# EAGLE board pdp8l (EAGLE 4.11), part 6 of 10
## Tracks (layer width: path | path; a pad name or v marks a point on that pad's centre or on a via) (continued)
MB_PARITY_ODD  (via drill 0.61) (continued)
  Route15 0.203: v162.97,264.82 163.37,264.82 165.81,262.38 171.91,262.38 211.73,222.56 211.73,221.34 232.87,200.2 233.68,200.2 246.69,187.2 246.69,185.57 250.75,181.51 250.75,179.48 251.97,178.26 B17.K1
  Bottom 0.203: v162.97,264.82 155.25,264.82 154.43,264.01 A24.D2
MEM00  (via drill 0.61)
  Top 0.203: v296.27,95.76 298.3,93.73 298.3,79.5 301.14,76.66 301.14,64.47 301.95,63.65 301.95,27.08 300.74,25.86 D13.R1 | v374.7,145.75 375.11,146.15 375.11,160.38 375.92,161.19 AB07.BR1 | v298.7,145.34 299.11,144.93 v299.11,138.02 | v267,138.84 266.6,138.43 266.6,131.93 265.38,130.71 C16.C1 | v26.82,272.95 26.82,272.54 19.1,264.82 19.1,194.92 19.91,194.11 B35.D1 | v239.78,281.48 239.78,273.76 A18.A1 240.18,272.54 241,271.73 241,205.49 244.65,201.83 244.65,177.44 v243.84,176.63 | v276.35,281.89 276.35,262.38 277.57,261.16 A15.E1
  Route15 0.203: v296.27,95.76 265.38,126.64 265.38,129.49 C16.C1 | v240.18,173.79 244.25,169.72 244.25,163.63 258.47,149.4 258.88,149.4 262.94,145.34 262.94,144.53 267,140.46 267,139.24 v267,138.84
  Bottom 0.203: v374.7,145.75 374.29,145.34 369.42,145.34 369.01,144.93 351.54,144.93 351.13,145.34 350.32,145.34 349.5,144.53 321.87,144.53 320.65,145.75 309.68,145.75 309.27,145.34 v298.7,145.34 | v299.11,138.02 298.7,138.43 288.54,138.43 287.73,139.24 267.41,139.24 v267,138.84 | v26.82,272.95 32.11,278.23 100.38,278.23 102.41,280.26 167.44,280.26 168.66,281.48 v239.78,281.48 239.78,281.89 251.16,281.89 251.97,281.08 252.78,281.08 253.19,281.48 253.19,281.89 253.59,282.3 275.95,282.3 v276.35,281.89 | v240.18,173.79 243.03,176.63 v243.84,176.63
MEM00\  (via drill 0.61)
  Top 0.203: v254.81,137.62 254.41,137.21 254.41,128.27 255.22,127.46 C16.D2
  Route2 0.203: v195.48,201.42 196.7,202.64 196.7,203.86 202.79,209.96 202.79,212.8 210.92,220.93 211.33,220.93 212.95,222.56 212.95,222.96 250.34,260.35 250.75,260.35 254.41,264.01 254.41,264.41 264.57,274.57 275.95,274.57 277.17,273.36 A15.A1
  Route15 0.203: v254.81,137.62 249.94,142.49 249.94,144.53 225.55,168.91 225.55,170.94 195.48,201.02 v195.48,201.42
MEM01  (via drill 0.61)
  Top 0.203: 363.32,136.8 366.57,140.06 v366.57,148.59 | 363.32,136.8 362.1,135.59 362.1,126.24 360.48,124.61 C08.E2 | v25.6,205.08 25.6,195.73 25.2,195.33 25.2,192.48 23.98,191.26 B35.E1 | v52.83,205.08 53.24,205.49 v53.24,216.05 | v232.46,216.05 232.87,216.46 232.87,221.74 A18.U2 233.68,222.96 234.9,224.18 234.9,249.38 v234.49,249.78 | 263.35,144.93 263.35,164.03 260.5,166.88 260.5,206.7 v260.1,207.11 | 263.35,144.93 263.35,128.27 262.53,127.46 C16.D1 | v273.51,249.78 273.51,255.88 274.32,256.69 A15.F1 | 363.32,136.8 359.26,140.87 v359.26,144.12 | v263.75,144.93 263.35,144.93
  Bottom 0.203: v366.57,148.59 369.42,148.59 AB07.BV2 | v52.83,205.08 v25.6,205.08 | v53.24,216.05 53.65,216.46 193.45,216.46 193.85,216.05 219.46,216.05 | 219.46,216.05 v232.46,216.05 | v260.1,207.11 259.69,206.7 248.72,206.7 248.31,206.3 236.93,206.3 228.8,214.43 221.08,214.43 219.46,216.05 | v273.51,249.78 273.1,249.38 234.9,249.38 v234.49,249.78 | v359.26,144.12 358.85,143.71 308.86,143.71 308.05,144.53 300.33,144.53 299.92,144.12 290.17,144.12 289.76,144.53 264.16,144.53 v263.75,144.93
MEM01\  (via drill 0.61)
  Top 0.203: v182.88,119.33 181.25,120.95 181.25,181.91 180.85,182.32 180.85,185.17 181.25,185.57 181.25,249.78 199.95,268.48 212.55,268.48 v212.55,268.88
  Bottom 0.203: v182.88,119.33 199.14,119.33 204.83,125.02 259.69,125.02 260.1,124.61 264.16,124.61 264.57,124.21 C16.E1 | v212.55,268.88 215.8,268.88 216.61,268.07 238.15,268.07 238.96,268.88 241,268.88 241.81,268.07 262.53,268.07 263.35,268.88 267.41,268.88 267.82,268.48 272.69,268.48 273.91,269.7 A15.B1
MEM02  (via drill 0.61)
  Top 0.203: v274.32,275.79 275.95,274.17 275.95,256.29 277.57,254.66 A15.H1 | C16.E2 258.47,124.61 257.25,125.83 v257.25,137.21 257.25,137.62 257.25,147.37 v257.66,147.78 | v23.98,179.48 23.98,183.54 B35.H1 | v388.52,138.43 390.14,140.06 390.14,160.38 389.33,161.19 AB06.BR1 | v215.39,231.09 215.8,231.5 215.8,251 225.55,260.76 225.55,271.73 226.37,272.54 A19.A1 | v262.94,183.95 263.75,183.13 263.75,168.5 266.6,165.66 266.6,151.84 265.38,150.62 v265.38,148.59
  Route2 0.203: v388.52,138.43 384.86,138.43 361.29,114.86 360.88,114.86 360.48,114.45 360.48,113.64 361.29,112.83 362.92,114.45 C08.J1
  Route15 0.203: v332.84,138.02 337.72,138.02 347.07,128.68 351.13,128.68 361.7,118.11 361.7,116.48 363.32,114.86 C08.J1 | v23.98,179.48 24.38,179.48 53.65,150.22 53.65,149.4 v57.3,145.75 | v215.39,231.09 215.39,229.87 225.55,219.71 226.37,219.71 239.37,206.7 240.18,206.7 v262.94,183.95
  Bottom 0.203: v274.32,275.79 273.91,275.39 229.62,275.39 227.58,273.36 A19.A1 | v257.25,137.21 258.06,138.02 275.13,138.02 275.95,138.84 287.32,138.84 288.14,138.02 297.89,138.02 299.11,136.8 301.55,136.8 302.77,138.02 319.84,138.02 320.24,137.62 321.46,137.62 321.87,138.02 v332.84,138.02 | v57.3,145.75 58.52,144.53 70.31,144.53 71.12,143.71 83.72,143.71 84.12,143.31 102.01,143.31 102.82,144.12 123.55,144.12 125.17,145.75 127.61,145.75 128.42,144.93 130.45,144.93 131.27,144.12 167.84,144.12 169.06,145.34 176.38,145.34 177.19,144.53 206.04,144.53 206.45,144.93 236.12,144.93 237.34,146.15 251.16,146.15 252.78,147.78 v257.66,147.78 258.06,147.78 264.57,147.78 v265.38,148.59
MEM02\  (via drill 0.61)
  Top 0.203: v253.59,143.71 254,143.31 254,122.58 255.22,121.36 C16.F2
  Route2 0.203: v253.59,143.71 253.59,145.34 258.47,150.22 v258.88,150.22 | v216.21,203.45 216.21,205.49 228.4,217.68 228.4,219.3 273.91,264.82 275.54,264.82 277.17,266.45 A15.C1
  Route15 0.203: v258.88,150.22 244.65,164.44 244.65,170.13 244.25,170.54 244.25,171.35 228.8,186.79 228.8,190.86 v216.21,203.45
MEM03  (via drill 0.61)
  Top 0.203: v238.96,147.78 238.56,148.18 238.56,175.01 238.15,175.41 238.15,188.42 237.74,188.82 v237.74,207.11 | v221.49,215.24 221.08,215.65 221.08,221.74 A19.U2 | v20.73,146.15 19.51,147.37 19.51,179.48 20.32,180.29 B35.J1 | v275.54,214.83 275.95,215.24 275.95,249.38 275.13,250.19 A15.J1 | v381.2,160.78 381.2,150.62 382.02,149.81 AB06.BV2
  Route2 0.203: v358.44,160.78 358.04,160.78 354.38,157.12 354.38,156.72 351.94,154.28 347.47,154.28 340.56,147.37 337.31,147.37 327.15,137.21 327.15,133.15 318.21,124.21 v317.81,124.21
  Route15 0.203: v238.96,147.78 250.75,135.99 250.75,135.18 261.72,124.21 261.72,121.36 C16.F1
  Bottom 0.203: v221.49,215.24 229.62,215.24 v237.74,207.11 237.74,206.7 247.9,206.7 256.85,215.65 263.35,215.65 264.16,214.83 v275.54,214.83 | v20.73,146.15 21.13,146.56 49.58,146.56 49.99,146.15 56.49,146.15 56.9,146.56 69.49,146.56 70.31,145.75 84.12,145.75 84.94,144.93 98.35,144.93 98.75,144.53 100.79,144.53 102.01,145.75 117.86,145.75 119.89,147.78 120.7,147.78 121.11,147.37 134.93,147.37 136.55,145.75 166.22,145.75 167.44,146.96 177.19,146.96 177.6,147.37 180.44,147.37 181.66,146.15 232.46,146.15 233.68,147.37 238.96,147.37 v238.96,147.78 | v358.44,160.78 v381.2,160.78 | v317.81,124.21 318.62,123.39 318.62,122.17 316.99,122.17 316.59,122.58 306.02,122.58 304.8,121.36 301.14,121.36 299.92,122.58 264.16,122.58 262.53,120.95 C16.F1
MEM03\  (via drill 0.61)
  Top 0.203: v206.86,168.5 206.45,168.91 206.45,214.02 209.7,217.27 209.7,220.52 v210.92,221.74
  Route2 0.203: v250.34,261.16 v210.92,221.74
  Route15 0.203: v206.86,168.5 230.43,144.93 234.9,144.93 262.13,117.7 264.57,117.7 C16.H1
  Bottom 0.203: v250.34,261.16 251.16,261.98 272.69,261.98 273.91,263.2 A15.D1
MEM04  (via drill 0.61)
  Top 0.203: v241,146.96 242.62,145.34 v242.62,135.18 | v288.54,157.53 286.11,157.53 v286.11,154.28 | A16.P2 258.47,234.34 257.66,233.53 257.66,229.46 257.25,229.06 257.25,224.18 256.85,223.77 256.85,138.02 256.44,137.62 256.44,134.77 256.85,134.37 256.85,119.74 258.47,118.11 C16.H2
  Route2 0.203: v402.34,166.06 401.93,165.66 401.93,162.41 AB05.BR1
  Route15 0.203: v60.96,145.75 60.15,144.93 56.9,144.93 54.05,147.78 51.61,147.78 36.58,162.81 35.36,162.81 34.95,163.22 34.95,163.63 24.38,174.19 21.13,174.19 B35.L1 | v242.62,135.18 243.03,135.18 256.85,121.36 256.85,119.74 258.47,118.11 C16.H2 | A20.A1 214.99,272.95 217.83,272.95 222.71,268.07 223.52,268.07 251.56,240.03 255.63,240.03 256.85,238.81 256.85,237.19 258.47,235.56 A16.P2
  Bottom 0.203: v60.96,145.75 61.37,145.34 71.53,145.34 72.34,144.53 97.94,144.53 98.35,144.12 101.19,144.12 102.41,145.34 123.14,145.34 124.36,146.56 131.27,146.56 132.89,144.93 167.03,144.93 168.25,146.15 177.19,146.15 177.6,145.75 232.87,145.75 234.09,146.96 v241,146.96 241.4,146.96 242.62,146.96 246.28,150.62 249.94,150.62 250.34,150.22 254,150.22 254.81,151.03 280.42,151.03 283.26,153.87 285.7,153.87 v286.11,154.28 | v402.34,166.06 401.52,166.88 338.53,166.88 337.72,166.06 336.09,166.06 335.69,166.47 319.84,166.47 314.15,160.78 310.9,160.78 309.68,162 308.05,162 306.83,163.22 297.08,163.22 291.39,157.53 v288.54,157.53
MEM04\  (via drill 0.61)
  Top 0.203: v250.34,171.75 250.75,171.35 250.75,153.47 247.9,150.62 247.9,148.18 253.59,142.49 253.59,116.48 255.22,114.86 C16.J2
  Route2 0.203: v222.71,202.64 237.74,217.68 237.74,218.49 244.25,224.99 244.25,229.06 255.63,240.44 255.63,242.47 256.85,243.69 256.85,245.31 258.47,246.94 A16.K2
  Route15 0.203: v250.34,171.75 247.9,174.19 247.9,177.85 230.84,194.92 226.77,194.92 222.71,198.98 v222.71,202.64
MEM05  (via drill 0.61)
  Top 0.203: v208.08,216.86 208.08,221.74 A20.U2 | A16.R2 255.22,231.09 254,229.87 254,218.49 v252.37,216.86 252.37,216.46 254,214.83 254,185.57 256.03,183.54 v256.03,183.13 | v395.43,146.96 395.43,148.59 AB05.BV2 | v25.6,145.34 25.6,169.72 24.38,170.94 B35.M1 | v269.85,169.32 270.26,168.91 v270.26,147.37
  Route2 0.203: v289.36,146.15 270.66,127.46 270.66,125.02 262.53,116.89 262.53,114.86 C16.J1
  Route15 0.203: v269.85,169.32 v256.03,183.13
  Bottom 0.203: v252.37,216.86 v208.08,216.86 | v395.43,146.96 395.02,147.37 356.82,147.37 356.01,146.56 349.1,146.56 348.29,145.75 325.12,145.75 323.09,147.78 321.06,147.78 320.24,146.96 317.4,146.96 316.59,147.78 312.12,147.78 311.71,148.18 308.46,148.18 306.43,146.15 v289.36,146.15 288.95,146.15 287.73,146.15 287.32,146.56 270.26,146.56 | v25.6,145.34 26.42,144.53 57.71,144.53 58.12,144.12 69.9,144.12 71.12,142.9 102.41,142.9 103.23,143.71 123.95,143.71 125.58,145.34 127.2,145.34 128.02,144.53 130.05,144.53 130.86,143.71 206.86,143.71 207.67,144.53 237.34,144.53 238.56,145.75 253.19,145.75 254,146.56 270.26,146.56 | 270.26,146.56 v270.26,147.37
MEM05\  (via drill 0.61)
  Top 0.203: v222.3,159.16 221.89,159.56 221.89,207.92 223.11,209.14 223.11,216.05 221.89,217.27 v221.89,220.52
  Route2 0.203: v221.89,220.52 v244.65,243.28
  Route15 0.203: v222.3,159.16 244.65,136.8 244.65,135.99 261.72,118.92 265.79,118.92 267.41,117.3 265.79,115.67 265.79,111.61 C16.K1
  Bottom 0.203: v244.65,243.28 254,243.28 254.81,244.09 A16.L2
MEM06  (via drill 0.61)
  Top 0.203: A16.S2 258.47,227.84 258.47,224.59 257.25,223.37 257.25,205.49 v257.66,205.08 257.66,204.67 257.25,204.27 257.25,149.4 259.28,147.37 259.28,146.15 v259.28,145.75 258.88,145.34 258.88,138.43 260.1,137.21 260.1,112.42 259.28,111.61 C16.K2 | v30.48,166.88 32.11,165.25 32.11,142.49 v33.33,141.28 | v415.75,143.71 415.75,159.97 414.53,161.19 AB04.BR1
  Bottom 0.203: v257.66,205.08 241.4,205.08 240.18,203.86 B18.A1 | v30.48,166.88 25.6,166.88 24.38,165.66 B35.P1 | v33.33,141.28 33.73,140.87 90.63,140.87 91.85,142.09 112.98,142.09 113.79,142.9 123.95,142.9 124.36,142.49 125.17,142.49 125.58,142.9 125.58,144.53 125.98,144.93 126.8,144.93 127.61,144.12 128.42,144.12 129.24,143.31 207.26,143.31 208.08,144.12 237.74,144.12 238.96,145.34 253.59,145.34 254,145.75 v259.28,145.75 259.69,145.75 261.31,144.12 289.36,144.12 289.76,143.71 300.33,143.71 300.74,144.12 307.64,144.12 308.46,143.31 360.88,143.31 361.7,144.12 365.76,144.12 366.17,143.71 373.07,143.71 373.48,144.12 392.58,144.12 393.8,142.9 414.93,142.9 v415.75,143.71
MEM06\  (via drill 0.61)
  Route2 0.203: v277.17,149.81 277.17,142.49 272.69,138.02 272.69,135.59 270.26,133.15 270.26,125.42 255.63,110.79 255.63,108.76 C16.L2 | v227.18,213.21 v254.81,240.84
  Route15 0.203: v277.17,149.81 277.17,150.22 262.53,164.85 262.53,165.66 254.41,173.79 254.41,179.07 249.53,183.95 249.53,185.17 247.9,186.79 247.9,191.26 234.09,205.08 234.09,206.3 v227.18,213.21
  Bottom 0.203: v254.81,240.84 258.06,240.84 A16.M2
MEM07  (via drill 0.61)
  Top 0.203: v233.27,139.65 233.27,151.84 B18.U2 232.87,153.06 232.05,153.87 232.05,174.6 231.24,175.41 231.24,177.04 v230.43,177.85 | v407.62,144.53 407.62,148.59 AB04.BV2 | v210.92,135.18 212.14,136.4 v212.14,139.24 | v255.22,203.05 256.03,203.86 256.03,217.68 254.81,217.68 254.41,218.08 254.41,224.18 255.22,224.99 A16.T2
  Route2 0.203: v372.67,144.53 371.86,144.53 350.72,123.39 350.32,123.39 349.91,122.99 349.91,121.77 v341.38,113.23 | v255.22,203.05 230.43,178.26 v230.43,177.85
  Route15 0.203: v233.27,139.65 258.06,114.86 258.06,114.45 261.72,110.79 261.72,108.76 C16.L1 | v103.63,159.97 107.29,159.97 117.04,150.22 117.04,149 v129.24,136.8
  Bottom 0.203: v407.62,144.53 407.21,144.93 386.49,144.93 386.08,144.53 v372.67,144.53 | v341.38,113.23 340.56,112.42 325.93,112.42 323.49,109.98 287.73,109.98 285.29,112.42 268.22,112.42 264.16,108.36 262.53,108.36 C16.L1 | v103.63,159.97 25.2,159.97 24.38,159.16 B35.S1 | v129.24,136.8 130.86,135.18 v210.92,135.18 | v212.14,139.24 212.55,139.65 232.87,139.65 v233.27,139.65
MEM07\  (via drill 0.61)
  Top 0.203: v224.74,112.01 225.15,112.42 225.15,129.08 219.46,134.77 219.46,172.16 219.86,172.57 219.86,176.63 219.46,177.04 219.46,206.7 v222.3,209.55
  Route2 0.203: v222.3,209.55 230.43,217.68 230.84,217.68 251.97,238.81 v251.97,239.22
  Bottom 0.203: v224.74,112.01 225.15,112.42 254.41,112.42 260.1,106.73 269.04,106.73 269.44,106.32 269.44,105.51 269.04,105.1 265.79,105.1 C16.M1 | v251.97,239.22 252.78,238.4 254.81,238.4 A16.N2
MEM08  (via drill 0.61)
  Top 0.203: v257.25,114.45 257.25,106.73 258.47,105.51 C16.M2 | v233.27,138.43 234.49,139.65 234.49,145.75 | 234.49,145.75 234.49,179.48 234.9,179.88 234.9,198.17 234.49,198.58 | 234.49,198.58 233.27,199.8 v233.27,201.02 | v234.09,145.75 234.49,145.75 | v269.85,216.05 269.85,233.12 271.07,234.34 A15.P2 | v234.49,216.05 234.09,215.65 234.09,204.67 234.49,204.27 234.49,198.58
  Route2 0.203: v417.78,149.81 426.72,158.75 426.72,161.19 AB03.BR1 | v329.59,146.56 329.59,146.15 318.62,135.18 318.21,135.18 305.21,122.17 305.21,121.77 v301.14,117.7
  Route15 0.203: v257.25,114.45 257.25,114.86 233.68,138.43 v233.27,138.43 | v59.74,145.75 36.58,168.91 36.58,169.32 14.63,191.26 14.63,192.89 B35.D2
  Bottom 0.203: v233.27,201.02 231.65,202.64 227.58,202.64 B19.A1 | v417.78,149.81 414.93,146.96 396.65,146.96 395.83,147.78 354.38,147.78 353.57,146.96 348.69,146.96 347.88,146.15 330,146.15 v329.59,146.56 | v301.14,117.7 299.52,116.08 278.38,116.08 275.13,112.83 259.28,112.83 257.66,114.45 v257.25,114.45 | v59.74,145.75 60.55,144.93 70.71,144.93 71.53,144.12 84.12,144.12 84.53,143.71 101.6,143.71 102.41,144.53 123.14,144.53 124.77,146.15 128.02,146.15 128.83,145.34 130.86,145.34 131.67,144.53 167.44,144.53 168.66,145.75 176.78,145.75 177.6,144.93 205.64,144.93 206.04,145.34 233.68,145.34 v234.09,145.75 | v234.49,216.05 v269.85,216.05
MEM08\  (via drill 0.61)
  Top 0.203: v208.08,150.22 206.04,152.25 206.04,222.56 213.77,230.28 218.64,230.28 218.64,241.25 v221.49,244.09
  Route15 0.203: v208.08,150.22 220.27,138.02 221.08,138.02 222.3,136.8 222.3,135.59 222.71,135.18 222.71,132.33 253.19,101.85 254.81,101.85 C16.N2
  Bottom 0.203: v221.49,244.09 223.11,245.72 235.31,245.72 235.71,246.13 269.44,246.13 270.66,247.34 A15.K2
MEM09  (via drill 0.61)
  Top 0.203: v223.11,135.99 221.08,138.02 221.08,151.84 B19.U2 | v416.56,131.93 419.81,135.18 419.81,148.18 420.22,148.59 AB03.BV2 | v303.17,103.07 302.77,102.67 v302.77,101.04 | v18.69,151.44 19.1,151.84 19.1,188.82 17.88,190.04 B35.E2 | v98.35,146.56 98.75,146.96 98.75,155.91 v99.57,156.72
  Route2 0.203: v352.75,133.55 352.75,133.15 v324.71,105.1 | v254.81,228.65 205.64,179.48 201.17,179.48 197.1,175.41 197.1,170.94 v185.32,159.16
  Route15 0.203: v254,105.1 v223.11,135.99
  Bottom 0.203: 260.1,103.07 259.69,103.48 255.63,103.48 v254,105.1 | 260.1,103.07 261.31,101.85 C16.N1 | v416.56,131.93 393.39,131.93 392.99,132.33 390.14,132.33 389.74,131.93 355.19,131.93 353.57,133.55 v352.75,133.55 | v324.71,105.1 323.09,103.48 303.58,103.48 v303.17,103.07 | v302.77,101.04 300.74,103.07 272.69,103.07 271.88,102.26 269.85,102.26 269.04,103.07 260.1,103.07 | v18.69,151.44 18.69,147.78 69.09,147.78 70.31,146.56 v98.35,146.56 | v99.57,156.72 99.97,157.12 129.64,157.12 130.05,157.53 154.03,157.53 156.46,159.97 174.75,159.97 175.16,160.38 177.6,160.38 181.25,156.72 185.32,156.72 | 185.32,156.72 201.57,156.72 204.42,153.87 210.92,153.87 213.77,151.03 218.64,151.03 219.86,152.25 B19.U2 | v254.81,228.65 256.44,230.28 262.53,230.28 262.94,230.68 267.41,230.68 267.82,231.09 A15.R2 | 185.32,156.72 v185.32,159.16
MEM09\  (via drill 0.61)
  Top 0.203: v258.06,214.83 260.5,217.27 260.5,233.53 v262.94,235.97
  Route2 0.203: v206.45,148.59 206.45,161.19 218.24,172.97 218.24,173.38 225.15,180.29 225.15,184.35 245.47,204.67 247.9,204.67 v258.06,214.83 | v262.94,235.97 264.57,237.59 264.57,238.81 266.6,240.84 266.6,242.06 268.22,243.69 A15.L2
  Route15 0.203: v254,98.6 254,99.01 249.94,103.07 245.87,103.07 216.21,132.74 216.21,138.84 v206.45,148.59
  Bottom 0.203: v254,98.6 255.63,98.6 256.85,99.82 263.75,99.82 264.57,99.01 C16.P1
MEM10  (via drill 0.61)
  Top 0.203: v212.55,134.37 212.95,134.77 212.95,201.83 213.77,202.64 B20.A1 214.58,203.86 214.58,205.49 v216.21,207.11 | v100.38,188.01 102.01,189.64 v102.01,198.58 | v268.63,210.36 268.63,211.58 270.66,213.61 270.66,216.46 270.26,216.86 270.26,227.03 271.07,227.84 A15.S2
  Route2 0.203: v384.86,162.41 382.02,165.25 364.54,147.78 361.29,147.78 349.5,135.99 349.5,135.59 v334.47,120.55
  Route15 0.203: v212.55,134.37 v230.02,116.89 254.81,92.1 258.47,95.76 258.47,97.79 C16.P2
  Bottom 0.203: v384.86,162.41 386.89,160.38 438.51,160.38 439.32,161.19 AB02.BR1 | v334.47,120.55 333.25,119.33 232.46,119.33 v230.02,116.89 | v100.38,188.01 88.59,176.22 66.24,176.22 63.4,179.07 54.86,179.07 54.46,178.66 53.24,178.66 53.24,179.88 53.65,180.29 53.65,181.51 52.83,182.32 42.67,182.32 39.42,185.57 18.69,185.57 17.88,184.76 B35.H2 | v102.01,198.58 125.17,198.58 128.42,201.83 133.3,201.83 133.71,202.23 136.96,202.23 137.77,201.42 156.87,201.42 159.72,198.58 162.15,198.58 162.56,198.98 165.81,198.98 166.22,198.58 174.75,198.58 177.6,201.42 194.26,201.42 195.07,200.61 197.1,200.61 198.32,201.83 212.95,201.83 213.77,202.64 B20.A1 | v268.63,210.36 264.57,206.3 249.12,206.3 248.72,205.89 236.53,205.89 235.71,206.7 216.61,206.7 v216.21,207.11
MEM10\  (via drill 0.61)
  Top 0.203: v218.24,135.59 218.64,135.99 218.64,172.16 218.24,172.57 218.24,173.38 218.64,173.79 v218.64,198.58
  Route2 0.203: v218.64,198.58 220.27,198.58 226.37,204.67 227.18,204.67 237.34,214.83 237.34,216.46 238.15,217.27 238.15,218.08 v259.69,239.62
  Route15 0.203: v218.24,135.59 255.22,98.6 255.22,95.76 C16.R2
  Bottom 0.203: v259.69,239.62 260.1,240.03 269.44,240.03 270.66,241.25 A15.M2
MEM11  (via drill 0.61)
  Top 0.203: v161.34,153.87 166.62,153.87 v166.62,151.03 | v227.58,220.52 227.99,220.12 227.99,206.3 225.55,203.86 v225.55,172.16
  Route2 0.203: v225.55,172.16 209.7,156.31 209.7,154.69 208.08,153.06 B20.U2 | v271.48,227.03 270.26,227.03 269.04,225.81 A15.T2
  Route15 0.203: C16.R1 261.31,95.76 261.31,99.01 223.52,136.8 223.52,138.84 211.73,150.62 209.7,150.62 208.48,151.84 B20.U2 | v54.86,175.41 56.08,175.41 v79.25,152.25 | v398.27,144.12 394.21,140.06 344.63,189.64 344.63,191.67 333.25,203.05 333.25,203.45 332.84,203.86 331.62,203.86 323.9,211.58 323.49,211.58 v306.83,228.24
  Bottom 0.203: v54.86,175.41 54.46,175.82 49.17,175.82 46.74,173.38 17.48,173.38 17.48,177.04 B35.K2 | v79.25,152.25 79.25,153.87 v161.34,153.87 | v166.62,151.03 206.04,151.03 207.26,152.25 B20.U2 | v227.58,220.52 229.62,220.52 232.87,223.77 240.18,223.77 241,222.96 243.84,222.96 245.06,224.18 262.94,224.18 263.35,224.59 267.41,224.59 267.82,224.99 A15.T2 | v398.27,144.12 398.68,143.71 408.03,143.71 408.84,144.53 428.35,144.53 432.82,149 AB02.BV2 | v306.83,228.24 306.43,227.84 304.39,227.84 303.99,227.43 294.64,227.43 294.23,227.84 291.8,227.84 291.39,227.43 282.04,227.43 281.63,227.84 279.2,227.84 278.38,227.03 v271.48,227.03
MEM11\  (via drill 0.61)
  Top 0.203: v224.33,137.21 222.71,138.84 222.71,158.34 223.11,158.75 223.11,160.78 222.3,161.59 222.3,182.32 v224.33,184.35 | v261.31,220.93 263.35,222.96 263.35,235.15 263.75,235.56 v263.75,238
  Route2 0.203: v224.33,184.35 245.06,205.08 246.28,205.08 252.78,211.58 252.78,212.39 v261.31,220.93
  Route15 0.203: v224.33,137.21 264.16,97.38 264.16,95.35 264.57,94.94 264.57,92.51 C16.S1
  Bottom 0.203: v263.75,238 267.82,238 A15.N2
MEM_ALT1\  (via drill 0.61)
  Top 0.203: v338.12,235.97 336.91,237.19 336.91,241.25 339.34,243.69 339.34,253.85 338.53,254.66 338.53,256.69 A10.F1 | v430.78,94.13 428.75,96.16 428.75,103.07 v429.16,103.48
  Route2 0.203: v338.12,235.97 338.12,235.56 332.03,229.46 332.03,226.21 A10.T2 | v449.48,63.65 441.76,55.93 441.76,54.71 437.69,50.65 437.69,46.58 419.81,28.7 418.19,28.7 D04.P1
  Route15 0.203: v449.48,63.65 449.48,64.47 447.85,66.09 447.85,68.94 444.6,72.19 444.6,79.91 433.22,91.29 432.82,91.29 432.41,91.69 432.41,92.51 v430.78,94.13 | v429.16,103.48 403.56,129.08 403.56,140.87 397.87,146.56 397.87,150.22 396.65,151.44 396.65,152.25 387.71,161.19 387.71,165.25 358.04,194.92 353.97,194.92 346.25,202.64 346.25,204.27 343.81,206.7 343.41,206.7 343,207.11 343,207.92 337.72,213.21 337.72,217.27 336.5,218.49 336.5,218.9 333.65,221.74 333.65,223.77 332.44,224.99 A10.T2
MEM_ALT2\  (via drill 0.61)
  Top 0.203: v321.06,224.18 321.06,230.68 321.87,231.5 321.87,234.34 A11.P2 | v418.59,63.25 418.59,62.84 419.81,61.62 419.81,59.18 419.4,58.78 419.4,47.4 416.15,44.15 416.15,27.08 414.93,25.86 D04.R1
  Route2 0.203: v418.59,63.25 418.59,63.65 426.72,71.78 426.72,72.59 449.88,95.76 449.88,96.98 450.7,97.79 450.7,102.26 451.92,103.48 451.92,104.7 v455.17,107.95 | v313.33,234.34 312.52,234.34 310.08,231.9 310.08,231.09 308.05,229.06 308.05,227.84 306.43,226.21 A12.T2
  Route15 0.203: v455.17,107.95 453.14,109.98 453.14,110.39 452.73,110.79 452.32,110.79 451.51,111.61 451.51,113.23 447.85,116.89 447.85,120.95 443.79,125.02 443.79,127.05 435.25,135.59 435.25,138.02 419,154.28 419,155.09 416.15,157.94 416.15,163.22 391.36,188.01 v391.36,188.42 | v360.88,188.01 359.26,188.01 339.75,207.52 339.75,210.36 337.31,212.8 337.31,215.65 329.18,223.77 324.71,223.77 321.06,227.43 321.06,229.06 320.24,229.87 319.02,229.87 317.4,231.5 317.4,231.9 315.77,233.53 314.15,233.53 v313.33,234.34
  Bottom 0.203: v321.06,224.18 307.64,224.18 306.83,224.99 A12.T2 | v391.36,188.42 388.93,190.86 387.3,190.86 386.08,192.07 366.17,192.07 362.1,188.01 v360.88,188.01
MEM_BEGIN\  (via drill 0.61)
  Top 0.203: v252.37,17.73 252.37,21.79 D17.S1 | B18.B1 236.12,200.61 236.12,214.43 235.71,214.83 235.71,216.05 238.15,218.49 238.15,268.07 236.93,269.29 A18.B1 | v220.68,56.74 218.64,58.78 218.64,67.72 215.39,70.97 215.39,81.94 203.2,94.13 203.2,180.7 v202.79,181.1
  Route2 0.203: 253.59,23.83 252.78,23.01 D17.S1 | 253.59,23.83 254.41,24.64 254.41,26.26 264.97,36.83 264.97,40.49 D16.K1 | v220.68,56.74 253.59,23.83 | v202.79,181.1 219.86,198.17 221.49,198.17 223.11,199.8 B19.B1
  Bottom 0.203: v252.37,17.73 256.44,17.73 258.06,16.1 D16.U2 | 221.89,201.42 212.95,201.42 211.73,200.2 B20.B1 | 221.89,201.42 223.11,200.2 B19.B1 | 221.89,201.42 230.84,201.42 232.05,200.2 236.12,200.2 B18.B1 | 221.89,268.48 217.02,268.48 215.8,269.7 211.73,269.7 A20.B1 | 221.89,268.48 223.11,269.7 A19.B1 | 221.89,268.48 235.31,268.48 236.12,269.29 A18.B1 237.34,269.7 241,269.7 242.21,268.48 247.9,268.48 248.72,269.29 A17.B1
MEM_DONE\  (via drill 0.61)
  Top 0.203: v409.65,103.89 409.65,114.45 408.03,116.08 408.03,120.14 C04.F2 | v403.56,103.48 403.15,103.07 403.15,94.94 402.34,94.13 402.34,90.07 403.15,89.26 403.15,84.38 v402.74,83.97 | v404.37,83.16 403.96,82.75 403.96,67.72 403.56,67.31 403.56,51.87 v403.96,51.46
  Route2 0.203: v402.74,83.97 403.96,82.75 v404.37,83.16 | v164.59,31.95 165,31.95 166.22,33.17 191.41,33.17 226.37,68.12 227.99,68.12 242.21,82.35 C17.V2
  Route15 0.203: v265.79,80.72 282.45,64.06 282.45,60 v287.73,54.71 | v164.59,31.95 156.46,40.08 149.96,40.08 128.42,61.62 120.7,61.62 112.17,70.16 108.1,70.16 107.29,70.97 106.48,70.97 52.83,124.61 51.61,124.61 39.01,137.21 39.01,138.43 28.45,149 27.64,149 B34.V2
  Bottom 0.203: 403.96,49.43 419.4,49.43 420.22,50.24 CD03.BF2 | 403.96,49.43 337.31,49.43 336.91,49.84 333.25,49.84 332.44,50.65 D10.F2 331.22,51.05 330,52.27 290.17,52.27 v287.73,54.71 | v265.79,80.72 244.65,80.72 243.43,81.94 C17.V2 | v409.65,103.89 409.25,103.48 v403.56,103.48 | v403.96,51.46 403.96,49.43
MEM_ENABLE(0-4)  (via drill 0.61)
  Top 0.203: v318.62,195.33 317.81,196.14 317.81,228.24 | 317.81,228.24 317.81,272.95 318.21,273.36 318.21,275.79 314.96,279.04 312.93,279.04 312.93,270.51 A12.B1 | 317.81,228.24 v320.24,230.68
  Route2 0.203: v359.26,231.9 360.07,232.72 360.07,234.34 A08.P2
  Route15 0.203: v364.13,151.03 325.53,189.64 325.53,190.04 324.31,191.26 323.9,191.26 320.24,194.92 319.43,194.92 319.02,195.33 v318.62,195.33
  Bottom 0.203: 384.45,150.62 384.45,151.84 385.27,151.84 AB06.BU2 386.49,152.25 387.71,151.03 397.05,151.03 397.87,151.84 AB05.BU2 | 384.45,150.62 384.45,150.22 384.86,149.81 388.52,149.81 AB06.BV1 | 384.45,150.62 382.02,150.62 381.61,150.22 377.14,150.22 376.73,149.81 AB07.BV1 375.92,149.81 373.89,151.84 373.48,151.84 AB07.BU2 372.26,152.25 371.04,151.03 v364.13,151.03 | v318.62,195.33 318.21,194.92 314.15,194.92 313.33,194.11 B12.D1 | v359.26,231.9 357.63,230.28 320.65,230.28 v320.24,230.68
MEM_ENABLE(5-11)  (via drill 0.61)
  Top 0.203: v318.21,147.78 317.4,146.96 317.4,144.53 317.81,144.12 317.81,126.24 316.18,124.61 C12.E1 | v399.49,153.87 399.9,153.47 399.9,151.03 401.12,149.81 AB05.BV1 | v378.76,214.43 377.95,213.61 377.95,188.82 v378.36,188.42
  Route2 0.203: v369.82,135.18 373.89,139.24 375.51,139.24 v388.93,152.65 | v383.24,235.56 388.93,229.87 379.58,220.52 379.58,215.24 v378.76,214.43
  Route15 0.203: v318.21,147.78 319.43,147.78 v334.47,132.74 | v378.36,188.42 378.36,188.01 400.3,166.06 400.3,159.16 402.34,157.12 404.37,157.12 407.21,154.28 408.84,154.28 410.46,152.65 AB04.BU2 | AB03.BV1 426.31,149.4 426.31,149.81 424.28,151.84 AB03.BU2
  Bottom 0.203: v334.47,132.74 335.28,131.93 340.16,131.93 343,134.77 352.75,134.77 353.16,134.37 356.01,134.37 356.41,134.77 365.35,134.77 365.76,134.37 369.01,134.37 v369.82,135.18 | v388.93,152.65 390.14,153.87 392.58,153.87 392.99,153.47 397.46,153.47 397.87,153.87 v399.49,153.87 | AB03.BV1 427.53,149.81 428.35,150.62 432,150.62 433.22,151.84 436.07,151.84 AB02.BU2 436.88,151.84 437.29,151.84 439.32,149.81 AB02.BV1 | v383.24,235.56 382.42,236.37 365.76,236.37 362.51,233.12 360.07,233.12 359.26,233.93 358.85,233.93 356.41,236.37 353.16,236.37 350.72,233.93 349.1,233.93 348.29,234.75 A09.P2 | 413.31,150.62 412.09,151.84 411.68,151.84 AB04.BU2 | 413.31,150.62 414.12,149.81 AB04.BV1 | 413.31,150.62 421.44,150.62 423.06,152.25 AB03.BU2 | 413.31,150.62 403.56,150.62 402.34,149.4 AB05.BV1
MEM_IDLE  (via drill 0.61)
  Top 0.203: v406.81,117.3 v406.81,72.59
  Route15 0.203: v406.81,72.59 407.21,72.59 408.03,71.78 409.25,71.78 v413.31,67.72
  Bottom 0.203: v406.81,117.3 410.46,117.3 C04.H2 | v413.31,67.72 414.12,66.9 416.97,66.9 D04.A1
MEM_P  (via drill 0.61)
  Top 0.203: v28.04,280.67 28.04,272.95 19.51,264.41 19.51,201.42 20.32,200.61 B35.B1 | v252.37,281.89 252.37,273.76 A17.A1 252.78,272.54 253.59,271.73 v253.59,252.22 | C16.A1 265.38,137.21 266.19,138.02 266.19,150.62 267,151.44 267,175.41 266.19,176.22 266.19,177.04 266.6,177.44 266.6,195.33 267,195.73 267,254.25 265.79,255.47 262.13,255.47 262.13,251.41 A16.J1
  Bottom 0.203: v28.04,280.67 28.45,280.26 95.1,280.26 95.5,280.67 158.5,280.67 160.12,282.3 251.97,282.3 v252.37,281.89 | v253.59,252.22 260.1,252.22 261.31,251 A16.J1
MEM_P\  (via drill 0.61)
  Top 0.203: v262.13,144.93 262.13,133.96 C16.B1 | v247.09,193.7 248.31,194.92 250.75,194.92 250.75,224.18 253.59,227.03 253.59,251 256.85,254.25 256.85,266.85 261.31,271.32 263.35,271.32 263.35,264.82 262.53,264.01 A16.D1
  Route2 0.203: v234.09,180.29 234.09,180.7 v247.09,193.7
  Route15 0.203: v262.13,144.93 236.53,170.54 236.53,172.97 235.31,174.19 235.31,179.07 v234.09,180.29
MEM_PARITY_EVEN
  Route2 0.203: A14.R1 288.14,231.9 288.14,232.31 290.17,234.34 A14.P1
  Route15 0.203: A16.L1 262.53,244.09 266.6,244.09 267.41,243.28 273.91,243.28 283.67,233.53 285.7,233.53 286.92,232.31 A14.R1
MEM_RET
  Top 0.508: A26.B2 128.02,269.29 127.2,268.48 127.2,204.27 128.02,203.45 128.02,200.61 B26.B2
  Route2 0.508: B28.L2 103.23,175.41 103.23,177.04 124.36,198.17 126.39,198.17 128.02,199.8 B26.B2
  Bottom 0.508: A26.B2 129.24,269.7 129.64,269.29 133.3,269.29 134.11,268.48 136.55,268.48 137.77,269.7 140.61,269.7 A25.B2 | B25.B2 140.61,200.2 140.21,200.61 136.55,200.61 135.74,201.42 133.71,201.42 132.49,200.2 129.24,200.2 B26.B2
MEM_START  (via drill 0.61)
  Top 0.203: v265.38,70.97 262.94,68.53 262.94,64.47 262.53,64.06 D16.B1 | v293.01,77.88 296.27,81.13 296.27,85.19 C13.U2 | v138.58,161.59 139.8,160.38 139.8,136.8 145.9,130.71 v145.9,105.92
  Route2 0.203: v351.54,29.11 359.26,36.83 364.54,36.83 373.48,45.77 375.51,45.77 385.67,55.93 389.74,55.93 405.99,72.19 405.99,73 407.62,74.62 407.62,77.88 430.78,101.04 432.82,101.04 C02.N2
  Route15 0.203: v351.54,29.11 349.1,29.11 319.84,58.37 315.77,58.37 308.05,66.09 308.05,68.53 306.83,69.75 306.83,73 302.77,77.06 302.77,77.88 298.7,81.94 298.7,83.97 297.49,85.19 C13.U2 | v216.21,103.89 219.46,103.89 242.21,81.13 246.28,81.13 260.1,67.31 260.1,65.68 261.72,64.06 D16.B1
  Bottom 0.203: v265.38,70.97 272.29,77.88 v293.01,77.88 | v138.58,161.59 137.77,161.59 136.14,163.22 134.52,163.22 132.08,160.78 89.81,160.78 89,161.59 86.97,161.59 86.16,160.78 74.78,160.78 69.09,166.47 54.86,166.47 52.02,163.63 39.42,163.63 38.61,162.81 35.36,162.81 34.95,163.22 32.51,163.22 30.89,164.85 B34.P2 | v145.9,105.92 166.62,105.92 169.06,103.48 215.8,103.48 v216.21,103.89
MEM_SUPPLY+  (via drill 0.61)
  Top 0.508: A26.J2 128.83,251.41 130.45,253.03 130.45,258.32 131.67,259.54 A26.E2 | 161.75,242.88 166.22,242.88 166.22,244.09 A23.L2 | 161.75,242.88 159.72,242.88 158.9,243.69 158.9,244.09 154.43,244.09 A24.L2 | A23.K1 175.97,246.94 174.75,245.72 174.75,230.28 175.56,229.46 175.56,229.06 A23.S1 | B24.U2 157.28,153.06 157.68,153.47 157.68,155.09 160.12,157.53 162.97,157.53 162.97,158.34 B24.S1 163.37,159.56 162.15,160.78 162.15,175.82 163.37,177.04 B24.K1 | B28.R2 102.82,162.41 102.82,167.69 B28.N2 | 141.83,183.95 143.87,185.98 143.87,190.04 B25.E2 144.27,191.26 144.27,192.89 139.8,197.36 139.8,212.8 142.65,215.65 142.65,220.52 143.87,221.74 A25.U2 | v140.61,182.73 141.83,183.95 | v119.08,175.01 119.08,172.16 B27.M2 | v148.34,176.22 147.52,177.04 147.52,178.26 141.83,183.95 | 161.75,242.88 161.75,222.96 v159.72,220.93
  Route15 0.508: A23.L2 167.44,244.5 171.09,244.5 175.16,248.56 175.56,248.16 A23.K1
  Bottom 0.508: A26.J2 129.24,250.6 130.45,249.38 139.4,249.38 140.61,250.6 A25.J2 141.83,250.6 143.46,248.97 174.75,248.97 175.56,248.16 A23.K1 | A23.U2 170.28,222.96 171.09,223.77 173.53,223.77 175.97,226.21 175.97,227.84 A23.S1 | B23.K1 175.56,177.85 171.91,177.85 169.06,175.01 167.44,175.01 B23.L2 166.22,175.01 164.19,177.04 163.78,177.04 B24.K1 162.97,177.44 161.75,176.22 155.65,176.22 154.43,175.01 B24.L2 153.21,175.01 151.99,176.22 v148.34,176.22 | B23.U2 170.28,153.06 171.5,154.28 173.94,154.28 175.97,156.31 175.97,157.94 B23.S1 175.56,158.34 172.31,158.34 171.09,157.12 165.41,157.12 164.19,158.34 B24.S1 | B28.P2 106.07,165.66 104.04,167.69 103.63,167.69 B28.N2 103.63,168.91 104.04,168.91 105.26,170.13 | 105.26,170.13 106.07,170.94 B28.M2 | 105.26,170.13 117.04,170.13 118.26,171.35 B27.M2 | 143.05,220.93 133.71,220.93 132.49,222.15 A26.U2 | 143.05,220.93 143.87,221.74 A25.U2 | 133.3,183.13 133.71,182.73 v140.61,182.73 | 133.3,183.13 132.49,183.95 B26.H2 | v119.08,175.01 119.08,176.22 119.89,176.22 126.8,183.13 133.3,183.13 | 143.05,220.93 v159.72,220.93
MEM_SUPPLY-  (via drill 0.61)
  Top 0.508: A26.M2 131.67,242.06 130.45,243.28 130.45,251.82 131.27,252.63 131.27,253.44 A26.H2 | v86.97,56.74 89,58.78 89,135.59 94.28,140.87 v94.28,149 | B28.T2 102.82,155.09 102.82,149.81 B28.V2 | B28.S2 106.07,157.94 106.07,153.06 B28.U2 | B25.J2 141.43,180.29 143.05,178.66 143.05,154.28 144.27,153.06 B25.U2 | v148.34,208.74 145.9,206.3 145.9,185.98 144.68,184.76 B25.H2
  Route2 0.508: v86.97,56.74 43.48,13.26 40.23,13.26 D33.V2 | v148.34,208.74 153.62,214.02 153.62,218.49 A24.V2
  Route15 0.508: A24.V2 153.21,219.3 151.59,219.3 133.3,237.59 133.3,239.62 132.08,240.84 A26.M2
  Bottom 0.508: A24.V2 154.43,218.49 155.25,217.68 165.41,217.68 166.22,218.49 A23.V2 | A25.H2 143.87,253.44 143.05,252.63 133.71,252.63 132.49,253.85 A26.H2 | B26.J2 129.24,180.7 130.45,179.48 139.4,179.48 140.61,180.7 B25.J2 141.83,181.51 142.24,181.51 144.27,183.54 B25.H2 | v94.28,149 95.91,150.62 101.19,150.62 102.41,149.4 B28.V2 103.63,149.81 104.04,149.81 105.26,151.03 | 105.26,151.03 106.07,151.84 B28.U2 | 114.61,150.62 114.2,151.03 105.26,151.03 | 114.61,150.62 115.42,149.81 B27.V2 | 130.45,151.03 130.05,150.62 114.61,150.62 | 130.45,151.03 131.27,151.84 B26.U2 | 143.05,151.03 143.87,151.84 B25.U2 | 130.45,151.03 143.05,151.03 | 151.99,150.62 151.59,151.03 143.05,151.03 | 151.99,150.62 153.21,149.4 B24.V2 | 151.99,150.62 165.41,150.62 166.22,149.81 B23.V2
MEMORY_INCREMENT  (via drill 0.61)
  Top 0.203: v137.77,214.83 139.8,216.86 139.8,221.74 146.71,228.65 v146.71,229.06 | v317.4,36.02 317.4,42.11 319.02,43.74 D11.J2 | v188.16,113.64 186.94,114.86 186.94,233.12 v186.54,233.53
  Route15 0.203: v42.67,216.05 40.23,218.49 A33.V2 | v303.58,233.12 304.39,233.12 305.61,231.9 A12.R2 | v261.72,39.68 258.47,39.68 251.16,46.99 251.16,51.05 189.38,112.83 188.98,112.83 v188.16,113.64
  Bottom 0.203: v42.67,216.05 43.08,215.65 45.92,215.65 53.65,207.92 55.68,207.92 56.9,206.7 82.09,206.7 82.5,207.11 92.25,207.11 92.66,206.7 118.67,206.7 126.8,214.83 v137.77,214.83 | v146.71,229.06 147.52,229.87 172.72,229.87 173.13,230.28 187.76,230.28 188.98,231.5 | 188.98,231.5 191.01,233.53 293.42,233.53 296.27,236.37 299.52,236.37 302.77,233.12 v303.58,233.12 | v317.4,36.02 316.99,36.42 303.58,36.42 300.74,39.27 262.13,39.27 v261.72,39.68 | v186.54,233.53 188.57,231.5 188.98,231.5
MFTP0  (via drill 0.61)
  Top 0.203: B08.D1 363.32,194.11 363.32,199.39 B08.B1 | v419.4,80.31 419.4,87.63 420.22,88.44 CD03.AT2 | v368.61,158.75 368.61,175.41 368.2,175.82 368.2,194.92 366.98,196.14 B08.C1
  Route15 0.203: v368.61,158.75 377.55,149.81 377.55,148.18 406.4,119.33 406.4,118.92 421.03,104.29 421.03,103.48 425.09,99.42 425.09,95.35 429.56,90.88 431.19,90.88 432.82,89.26 C02.T2
  Bottom 0.203: B08.C1 367.39,196.95 369.01,198.58 370.64,198.58 371.04,198.98 371.04,201.42 365.35,201.42 364.13,200.2 B08.B1 | v419.4,80.31 281.23,80.31 277.57,83.97 273.1,83.97 271.88,85.19 C15.U2 | C02.T2 432.82,88.44 432,87.63 423.88,87.63 422.66,88.85 421.44,88.85 CD03.AT2
MFTP1  (via drill 0.61)
  Top 0.203: C05.P2 398.68,99.01 399.49,99.82 v399.49,102.67 399.9,102.67 399.9,85.19 395.83,81.13 395.83,78.69 v393.8,76.66 | v247.9,5.54 247.5,5.94 247.5,39.27 246.28,40.49 D17.K2 | v354.79,5.94 368.61,19.76 v368.61,73
  Route2 0.203: v399.49,102.67 416.97,120.14 418.19,120.14 420.22,122.17 421.44,122.17 423.06,123.8 CD03.AE2
  Bottom 0.203: D17.L2 243.43,38.46 245.47,40.49 245.87,40.49 D17.K2 | v247.9,5.54 260.5,5.54 261.72,4.32 292.61,4.32 293.83,5.54 300.74,5.54 303.17,3.1 343.41,3.1 346.25,5.94 v354.79,5.94 | v368.61,73 369.01,73.41 390.14,73.41 393.39,76.66 v393.8,76.66
MFTP2  (via drill 0.61)
  Top 0.203: v439.73,97.79 440.94,99.01 440.94,105.92 439.73,107.14 C02.L1 | v418.59,69.34 419.4,68.53 419.4,62.84 420.62,61.62 420.62,57.96 CD03.BD2 | v307.24,241.25 307.64,240.84 307.64,224.99 305.21,222.56 305.21,208.33 306.43,207.11 v306.43,203.05 | v310.9,198.58 311.3,198.17 v311.3,153.87 | v314.15,151.84 314.55,151.44 314.55,93.32 314.15,92.91 314.15,80.31 313.74,79.91 313.74,79.1 314.15,78.69 316.18,78.69 316.18,77.47 316.99,76.66 316.99,68.12 316.18,67.31 D12.A1
  Route2 0.203: C02.P2 436.07,97.79 436.07,93.73 428.75,86.41 428.75,79.1 419,69.34 v418.59,69.34
  Route15 0.203: v307.24,241.25 307.64,241.66 307.64,244.91 305.21,247.34 303.99,247.34 A13.K1 | v310.9,198.58 v306.43,203.05
  Bottom 0.203: v439.73,97.79 437.69,97.79 437.29,98.2 C02.P2 | v418.59,69.34 329.18,69.34 327.56,67.72 323.9,67.72 323.49,68.12 317.81,68.12 316.59,66.9 D12.A1 | v311.3,153.87 313.33,151.84 v314.15,151.84
MFTS0  (via drill 0.61)
  Top 0.203: v425.09,55.52 425.09,103.48 424.28,104.29 CD03.AM2
  Route2 0.203: v364.13,54.71 353.97,44.55 351.54,44.55 D09.J1
  Bottom 0.203: v364.13,54.71 364.54,55.12 416.15,55.12 | 416.15,55.12 416.97,54.3 D04.E1 | v425.09,55.52 424.69,55.12 416.15,55.12
MFTS1  (via drill 0.61)
  Route2 0.203: v331.62,78.69 332.03,78.69 352.75,99.42 352.75,100.23 369.01,116.48 v369.42,116.48
  Route15 0.203: v303.58,108.36 303.58,106.32 318.62,91.29 319.43,91.29 331.62,79.1 v331.62,78.69
  Bottom 0.203: v303.58,108.36 304.39,109.17 311.3,109.17 312.12,108.36 C12.L1 | v369.42,116.48 372.26,119.33 385.67,119.33 388.52,122.17 410.46,122.17 418.19,114.45 420.22,114.45 CD03.AJ2
MFTS1\  (via drill 0.61)
  Top 0.203: v425.91,52.68 425.91,90.88 425.5,91.29 425.5,109.17 424.28,110.39 CD03.AK2 | v275.54,86 275.95,86.41 275.95,108.76 273.51,111.2 273.51,116.89 275.95,119.33 275.95,125.02 274.73,126.24 C15.D1 | v346.25,19.76 349.1,16.92 349.1,3.1 418.59,3.1 418.59,14.88 419,15.29 419,18.54 412.9,24.64 412.9,49.02 414.12,50.24 D04.F1
  Route15 0.203: v275.54,86 296.27,65.28 301.55,65.28 310.08,56.74 310.9,56.74 321.46,46.18 325.93,46.18 333.25,38.86 333.25,32.77 v346.25,19.76
  Bottom 0.203: v425.91,52.68 423.06,52.68 422.66,52.27 416.15,52.27 414.93,51.05 D04.F1
MFTS2  (via drill 0.61)
  Top 0.203: 310.08,224.99 308.05,227.03 308.05,248.97 306.83,250.19 A12.J2 | 310.08,224.99 310.9,224.18 310.9,221.74 310.49,221.34 310.49,219.3 312.12,219.3 A12.V1 | v421.84,137.62 421.84,122.17 421.03,121.36 CD03.AF2 | 310.08,224.99 308.05,222.96 308.05,213.21 307.64,212.8 307.64,201.83 308.05,201.42 308.05,194.92 v309.27,193.7
  Route15 0.203: v375.51,136.8 374.7,136.8 364.54,146.96 361.7,146.96 354.79,153.87 349.91,153.87 346.66,157.12 345.85,157.12 336.5,166.47 336.5,168.1 333.65,170.94 333.65,172.97 332.44,174.19 B10.L2 331.62,175.41 330,177.04 330,178.26 328.78,179.48 324.71,179.48 318.62,185.57 317.4,185.57 v309.27,193.7
  Bottom 0.203: v421.84,137.62 420.62,138.84 393.8,138.84 393.39,138.43 389.74,138.43 388.93,139.24 377.14,139.24 375.51,137.62 v375.51,136.8
MFTS2\  (via drill 0.61)
  Top 0.203: v416.15,63.65 416.15,49.02 416.97,48.21 D04.H1 | v417.78,77.47 416.15,79.1 416.15,93.32 419,96.16 419,100.23 417.78,101.45 417.78,103.07 419,104.29 419,114.86 v418.59,115.27
  Route2 0.203: v268.63,92.51 273.51,97.38 273.51,115.27 275.54,117.3 275.54,118.92 277.17,120.55 277.17,123.39 C15.E1 | v410.46,38.86 410.87,38.86 415.75,43.74 415.75,45.36 417.37,46.99 D04.H1
  Route15 0.203: v416.15,63.65 416.15,66.9 415.34,67.72 415.34,69.34 420.62,74.62 v417.78,77.47 | v268.63,92.51 268.63,90.47 275.95,83.16 275.95,82.35 288.14,70.16 289.76,70.16 314.55,45.36 315.37,45.36 v321.87,38.86
  Bottom 0.203: v418.59,115.27 420.62,117.3 423.06,117.3 CD03.AH2 | v321.87,38.86 322.27,39.27 340.56,39.27 341.38,38.46 343,38.46 343.81,39.27 410.06,39.27 v410.46,38.86
MFTS3  (via drill 0.61)
  Top 0.203: v395.02,190.86 396.65,189.23 396.65,148.18 396.24,147.78 396.24,146.15 395.02,144.93 v395.02,136.4
  Route2 0.203: v455.17,62.03 451.1,57.96 451.1,51.46 444.6,44.96 444.6,42.93 443.38,41.71 D02.K1
  Route15 0.203: v367.39,44.15 360.48,51.05 359.66,51.05 341.38,69.34 337.31,69.34 326.75,79.91 326.75,83.16 319.02,90.88 318.21,90.88 317.4,91.69 316.59,91.69 C12.S1 | v339.34,235.97 338.53,236.78 337.31,236.78 336.09,238 332.44,238 A10.N2 | v349.5,234.75 349.91,234.75 355.6,229.06 355.6,228.65 357.63,226.62 358.04,226.62 388.52,196.14 388.52,195.73 388.93,195.33 390.55,195.33 v395.02,190.86 | v395.02,136.4 416.97,114.45 416.97,113.64 432.41,98.2 432.41,97.79 433.63,96.57 434.04,96.57 452.32,78.28 452.32,77.88 453.54,76.66 453.54,64.47 453.95,64.06 453.95,63.25 v455.17,62.03
  Bottom 0.203: v367.39,44.15 368.61,42.93 384.86,42.93 385.67,43.74 387.71,43.74 391.36,40.08 441.35,40.08 442.16,40.89 D02.K1 | v339.34,235.97 339.75,236.37 343,236.37 343.81,235.56 345.03,235.56 347.07,237.59 347.88,237.59 349.5,235.97 v349.5,234.75
MP_INT\  (via drill 0.61)
  Top 0.203: v278.79,186.79 279.2,187.2 279.2,229.06 279.6,229.46 279.6,255.07 280.42,255.88 280.42,256.69 A14.F2 | v200.76,81.13 v204.83,85.19 | v249.94,153.87 247.5,151.44 247.5,117.3 249.12,115.67 251.16,115.67 251.16,115.27 254.41,112.01 254.41,105.92 254.81,105.51 254.81,102.67 254.41,102.26 254.41,99.42 256.85,96.98 256.85,90.88 255.63,89.66 C16.T2
  Route2 0.203: v249.94,153.87 276.35,180.29 276.35,184.76 278.38,186.79 v278.79,186.79
  Bottom 0.203: v278.79,186.79 275.13,186.79 B15.F1 | v200.76,81.13 199.95,80.31 131.27,80.31 129.24,82.35 C26.V2 | v204.83,85.19 205.64,84.38 249.12,84.38 253.59,88.85 254.81,88.85 C16.T2
MP_SKIP\  (via drill 0.61)
  Top 0.203: v279.2,164.03 279.6,164.44 279.6,172.57 279.2,172.97 279.2,178.26 278.79,178.66 278.79,179.88 279.6,180.7 279.6,226.21 280.01,226.62 280.01,230.28 280.82,231.09 A14.R2
  Route2 0.203: v196.29,157.53 176.78,138.02 175.16,138.02 132.89,95.76 129.24,95.76 C26.R2
  Bottom 0.203: v196.29,157.53 199.14,160.38 251.56,160.38 254.81,163.63 269.44,163.63 270.66,164.85 B15.P2 271.88,164.44 273.51,164.44 274.32,163.63 278.79,163.63 v279.2,164.03
N$1
  Bottom 0.203: C02.S2 437.29,91.69 438.1,90.88 443.79,90.88 447.45,94.54 447.45,96.57 441.76,96.57 440.54,95.35 C02.R1
N$2  (via drill 0.61)
  Top 0.203: v434.04,103.48 433.63,103.89 433.63,107.14 C02.L2
  Bottom 0.203: v434.04,103.48 438.1,103.48 439.32,102.26 C02.N1
N$3  (via drill 0.61)
  Top 0.203: v436.07,58.37 437.69,58.37 437.69,103.48 436.88,104.29 C02.M2
  Route15 0.203: C02.P1 442.57,99.01 442.57,100.63 440.13,103.07 438.91,103.07 437.29,104.7 C02.M2
  Bottom 0.203: v436.07,58.37 415.75,58.37 414.93,57.56 D04.D1
N$4
  Top 0.203: D05.R2 395.83,25.04 400.3,25.04 400.3,24.64 401.52,23.42 404.37,23.42 404.37,27.08 403.56,27.89 403.56,49.84 404.77,51.05 404.77,53.49 D05.E1
N$5  (via drill 0.61)
  Top 0.203: v403.56,24.23 403.56,25.45 399.9,29.11 399.9,45.77 398.68,46.99 D05.H2
  Bottom 0.203: v403.56,24.23 430.78,24.23 431.6,25.04 432.82,25.04 D02.R2
N$6  (via drill 0.61)
  Top 0.203: v405.59,102.26 405.99,101.85 405.99,95.35 403.56,92.91 403.56,73.41 400.3,70.16 400.3,52.68 401.52,51.46 D05.F1
  Route2 0.203: v405.59,102.26 416.97,113.64 416.97,116.89 C04.H1
N$7
  Bottom 0.203: D04.J1 414.93,44.15 416.15,42.93 433.63,42.93 434.04,43.33 438.91,43.33 439.32,43.74 D02.J1
N$8  (via drill 0.61)
  Top 0.203: v386.89,52.68 386.89,36.42 386.08,35.61 D06.M2
  Route15 0.203: D05.H1 404.37,48.21 399.9,48.21 395.83,52.27 393.8,52.27 392.58,53.49 D06.E1
  Bottom 0.203: v386.89,52.68 388.11,53.9 391.36,53.9 D06.E1
N$9
  Top 0.203: D06.T2 382.42,19.76 380.8,21.39 380.8,45.77 379.58,46.99 D07.H1
  Bottom 0.203: D06.H1 391.36,47.8 390.14,49.02 380.8,49.02 379.98,48.21 D07.H1
N$10  (via drill 0.61)
  Top 0.203: v371.86,55.93 371.86,49.02 372.67,48.21 D07.H2 | v405.18,55.93 405.99,56.74 405.99,69.75 405.59,70.16 405.59,84.38 405.99,84.78 405.99,90.47 405.18,91.29 C05.S1
  Bottom 0.203: v371.86,55.93 v405.18,55.93
N$11  (via drill 0.61)
  Top 0.203: v431.6,23.83 431.6,78.69 430.38,79.91 v430.38,80.31
  Bottom 0.203: v431.6,23.83 440.94,23.83 442.16,22.61 D02.S1 | v430.38,80.31 429.56,81.13 420.22,81.13 419,82.35 419,87.22 412.9,87.22 411.68,86 C04.U2
N$12
  Route2 0.203: C05.D1 402.34,127.46 404.37,129.49 C05.C1
N$13  (via drill 0.61)
  Top 0.203: v367.39,42.93 366.57,43.74 366.57,46.99 D08.H1
  Bottom 0.203: v367.39,42.93 367.79,42.52 371.04,42.52 372.26,41.3 D07.K2
N$14  (via drill 0.61)
  Top 0.203: v382.42,42.11 381.2,43.33 381.2,52.27 379.98,53.49 D07.E1
  Route2 0.203: v382.42,42.11 372.26,31.95 370.64,31.95 D07.N2
N$15  (via drill 0.61)
  Top 0.203: v375.11,46.58 376.33,46.58 376.33,50.24 D07.F1 376.73,51.46 377.55,52.27 377.55,66.9 379.17,68.53 379.17,81.53 v379.98,82.35
  Route2 0.203: v379.98,82.35 385.27,87.63 385.27,88.04 398.27,101.04 398.27,104.29 C05.M2
  Route15 0.203: C05.M2 397.87,105.1 397.46,105.1 395.43,107.14 C05.L2
  Bottom 0.203: v375.11,46.58 374.7,46.18 361.7,46.18 360.88,46.99 D08.H2
N$16
  Top 0.203: D08.V2 357.63,13.26 358.85,14.48 358.85,17.73 368.2,27.08 368.2,52.68 367.39,53.49 D08.E1
N$17
  Top 0.203: AB31.BV1 71.93,149.81 73.15,151.03 73.15,220.93 73.97,221.74 AB31.AU1
N$18  (via drill 0.61)
  Top 0.203: v14.63,157.53 15.44,158.34 15.44,171.75 13.01,174.19 13.01,188.82 v14.22,190.04
  Route2 0.203: v14.22,190.04 67.06,242.88 67.87,242.88 70.71,245.72 72.34,245.72 73.97,247.34 AB31.AK1
  Route15 0.203: v14.63,157.53 15.85,156.31 15.85,151.03 17.48,149.4 17.48,145.34 18.69,144.12 18.69,137.21 36.17,119.74 36.17,118.11 C34.H1
N$19  (via drill 0.61)
  Top 0.203: v360.88,25.45 360.88,23.83 360.48,23.42 355.19,23.42 355.19,49.43 352.75,51.87 352.75,77.88 353.97,79.1 v353.97,83.16 | v356.41,83.97 357.23,84.78 357.23,87.22 358.85,88.85 358.85,94.94 362.1,98.2 362.1,117.3 v362.92,118.11
  Route2 0.203: v353.97,83.16 353.97,82.75 355.19,81.53 356.01,82.35 356.01,83.57 v356.41,83.97 | v362.92,118.11 377.55,132.74 377.55,134.37 379.17,135.99 C07.A1
  Bottom 0.203: v360.88,25.45 360.07,25.45 358.85,24.23 352.35,24.23 351.54,25.04 D09.R1
N$20  (via drill 0.61)
  Top 0.203: v390.96,114.05 390.55,113.64 390.55,107.14 390.96,106.73 390.96,99.82 391.77,99.01 C06.P1
  Route15 0.203: v390.96,114.05 394.21,117.3 379.98,131.52 377.95,131.52 376.73,132.74 C07.B1
N$21  (via drill 0.61)
  Route15 0.203: v421.03,84.38 421.03,84.78 401.93,103.89 401.93,107.14 C05.L1
  Bottom 0.203: v421.03,84.38 431.19,84.38 432.82,82.75 C02.V2
N$22
  Route15 0.203: D01.N1 452.73,32.36 452.73,36.42 455.57,39.27 454.36,40.49 454.36,57.56 448.67,63.25 448.67,64.47 445.82,67.31 445.82,68.12 425.91,88.04 425.91,89.26 423.88,91.29 CD03.AS2
N$23  (via drill 0.61)
  Top 0.203: v319.02,71.37 319.02,70.97 320.24,69.75 320.24,49.84 316.99,46.58 316.99,42.11 316.59,41.71 D12.K1 | v343.81,77.06 349.5,82.75 v349.5,85.19 | v380.39,116.08 380.8,116.48 380.8,119.74 379.58,120.95 379.58,121.77 380.8,122.99 380.8,125.83 379.58,127.05 379.58,129.49 C07.C1
  Route2 0.203: v349.5,85.19 349.91,85.19 356.41,91.69 356.41,92.1 v380.39,116.08
  Bottom 0.203: v319.02,71.37 323.9,76.25 343,76.25 v343.81,77.06
N$24
  Bottom 0.203: D11.N2 319.84,31.95 321.46,33.58 333.65,33.58 334.47,34.39 D10.M2
N$25
  Bottom 0.203: D12.N2 306.83,31.14 308.05,29.92 314.55,29.92 315.37,29.11 D12.P1
N$26
  Top 0.203: C08.H1 366.98,118.11 368.61,119.74 368.61,125.02 369.82,126.24 C07.D2 369.42,127.46 369.42,129.49 366.57,132.33 366.57,133.15 364.13,133.15 C08.B1
  Bottom 0.203: C08.D2 357.63,127.46 358.04,127.86 362.51,127.86 362.92,128.27 364.95,128.27 365.76,127.46 369.42,127.46 C07.D2
N$27  (via drill 0.61)
  Top 0.203: v334.47,73.41 333.65,74.22 333.65,99.42 v336.5,102.26
  Route2 0.203: v334.47,73.41 330,68.94 330,66.09 320.24,56.34 320.24,49.84 312.12,41.71 310.08,41.71 D12.K2 | v336.5,102.26 336.5,103.07 349.5,116.08 350.72,116.08 359.66,125.02 360.07,125.02 360.48,125.42 360.48,126.64 357.63,129.49 362.92,134.77 364.95,134.77 366.17,135.99 C08.A1
N$28  (via drill 0.61)
  Route2 0.203: v340.56,77.47 336.09,73 336.09,63.65 310.9,38.46 310.9,33.98 303.58,26.67 303.58,23.01 D13.S1 | v310.08,113.64 310.08,116.08 314.96,120.95 316.99,120.95 319.02,118.92 319.43,119.33 319.84,119.33 320.24,119.74 320.24,121.36 320.65,121.77 320.65,124.21 334.47,138.02 335.28,138.02 v346.25,149
  Route15 0.203: v340.56,77.47 339.34,77.47 324.31,92.51 324.31,94.13 321.06,97.38 321.06,101.85 317.81,105.1 317.81,105.92 v310.08,113.64 | v346.25,149 347.47,149 351.54,144.93 351.54,143.31 362.92,131.93 364.95,131.93 366.17,130.71 C08.C1
N$29  (via drill 0.61)
  Route2 0.203: v325.93,77.88 330.4,82.35 330.4,83.16 331.22,83.97 332.03,83.97 333.25,85.19 334.47,85.19 C10.U2
  Route15 0.203: v325.93,77.88 325.93,72.59 360.07,38.46 360.07,38.05 v385.27,12.85
  Bottom 0.203: v385.27,12.85 386.49,14.07 440.54,14.07 442.16,15.7 D02.U1
N$30  (via drill 0.61)
  Top 0.203: v367.79,86.82 368.2,87.22 368.2,99.82 366.98,101.04 366.98,103.07 368.2,104.29 368.2,107.54 v367.79,107.95
  Route15 0.203: v367.79,86.82 382.02,72.59 371.86,62.43 371.86,59.59 372.26,59.18 372.26,57.96 407.62,22.61 407.62,19.76 D04.T2
  Bottom 0.203: v367.79,107.95 369.42,107.95 C07.L2
N$31
  Top 0.203: D04.V2 408.43,13.26 412.9,13.26 414.93,15.29 416.97,15.29 D04.U1
N$32  (via drill 0.61)
  Route15 0.203: v371.45,72.19 369.01,69.75 358.44,69.75 358.04,70.16 344.63,70.16 332.44,82.35 C10.V2 | v393.8,74.62 392.99,75.44 392.99,82.75 371.86,103.89 371.86,109.58 372.67,110.39 C07.K2
  Bottom 0.203: v371.45,72.19 371.86,72.59 391.77,72.59 392.18,73 392.18,74.62 v393.8,74.62
N$33  (via drill 0.61)
  Route2 0.203: v8.94,172.16 8.94,173.38 18.69,183.13 18.69,189.64 28.45,199.39 28.45,203.45 67.46,242.47 69.09,242.47 70.71,244.09 AB31.AL1
  Route15 0.203: v37.39,118.92 37.39,119.33 19.1,137.62 19.1,144.53 17.88,145.75 17.88,149.81 16.26,151.44 16.26,157.94 9.75,164.44 9.75,169.32 9.35,169.72 9.35,171.75 v8.94,172.16
  Bottom 0.203: v37.39,118.92 37.8,118.92 37.8,116.89 36.98,116.08 35.76,116.08 34.14,114.45 C34.J1
N$34  (via drill 0.61)
  Top 0.203: v9.75,135.59 9.35,135.99 9.35,149.81 6.5,152.65 6.5,196.95 v7.32,197.76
